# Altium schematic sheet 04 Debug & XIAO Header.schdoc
size 400 x 277 mm; Device: default420x297; Symbol: default420x297; Name: default420x297; Size: "A3"; Id: /; File: 04 Debug & XIAO Header; Sheet: /
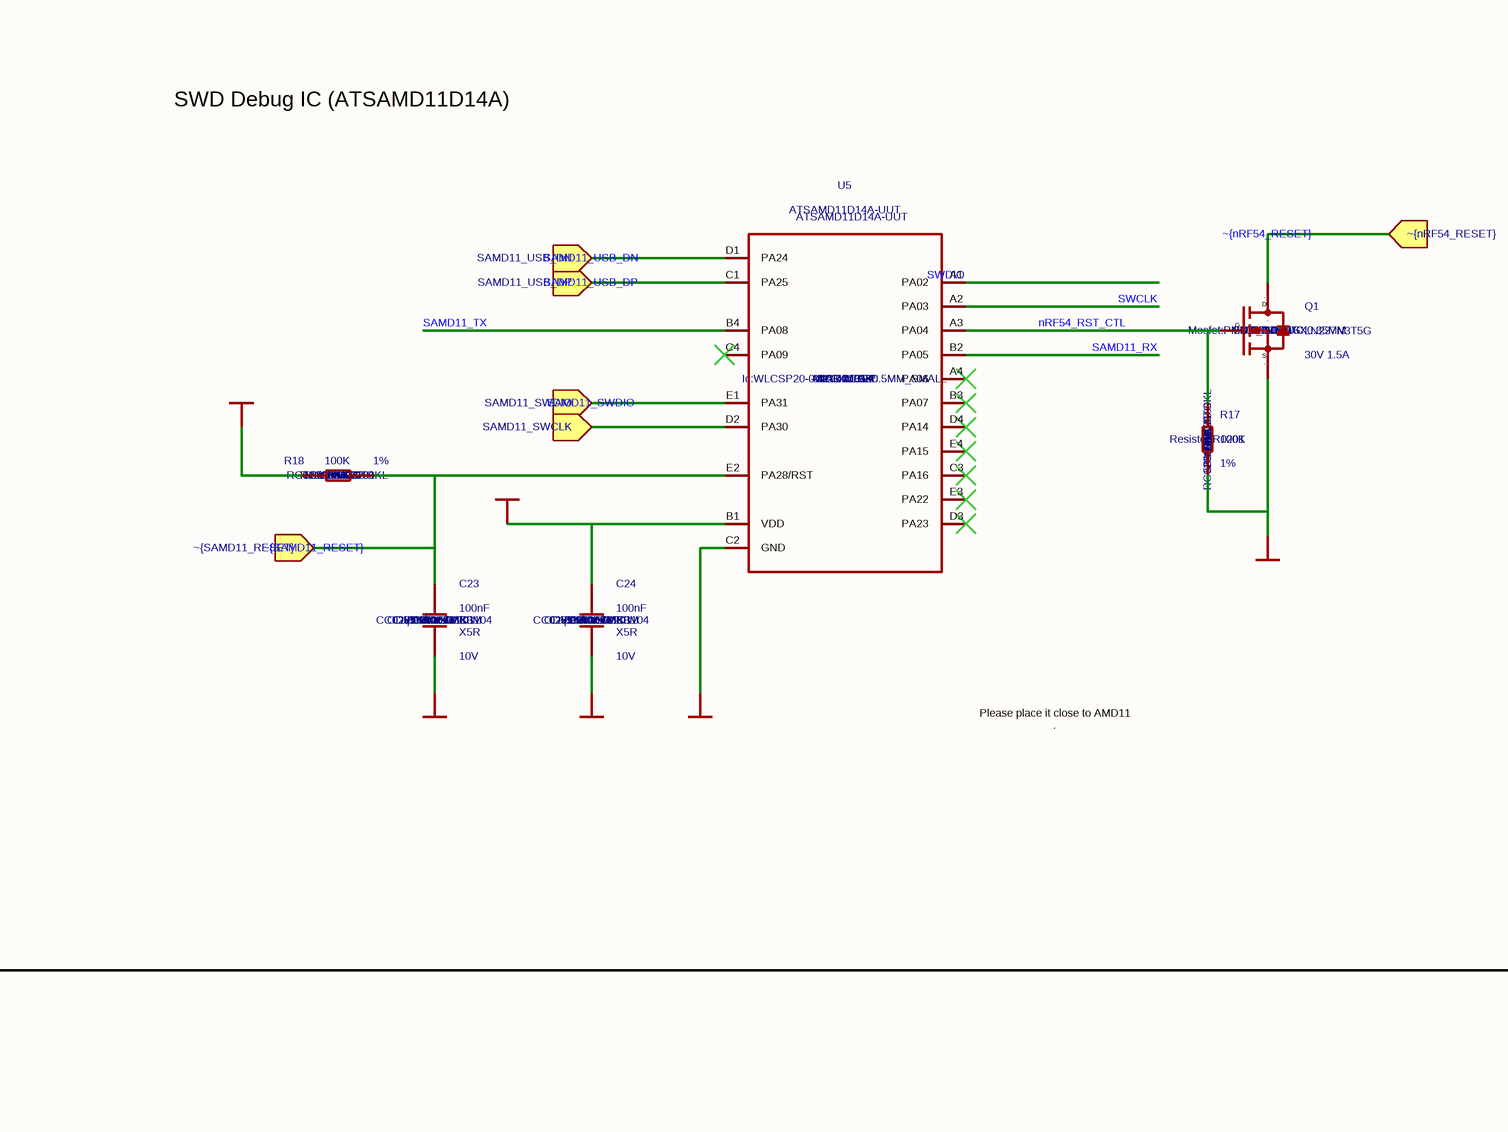
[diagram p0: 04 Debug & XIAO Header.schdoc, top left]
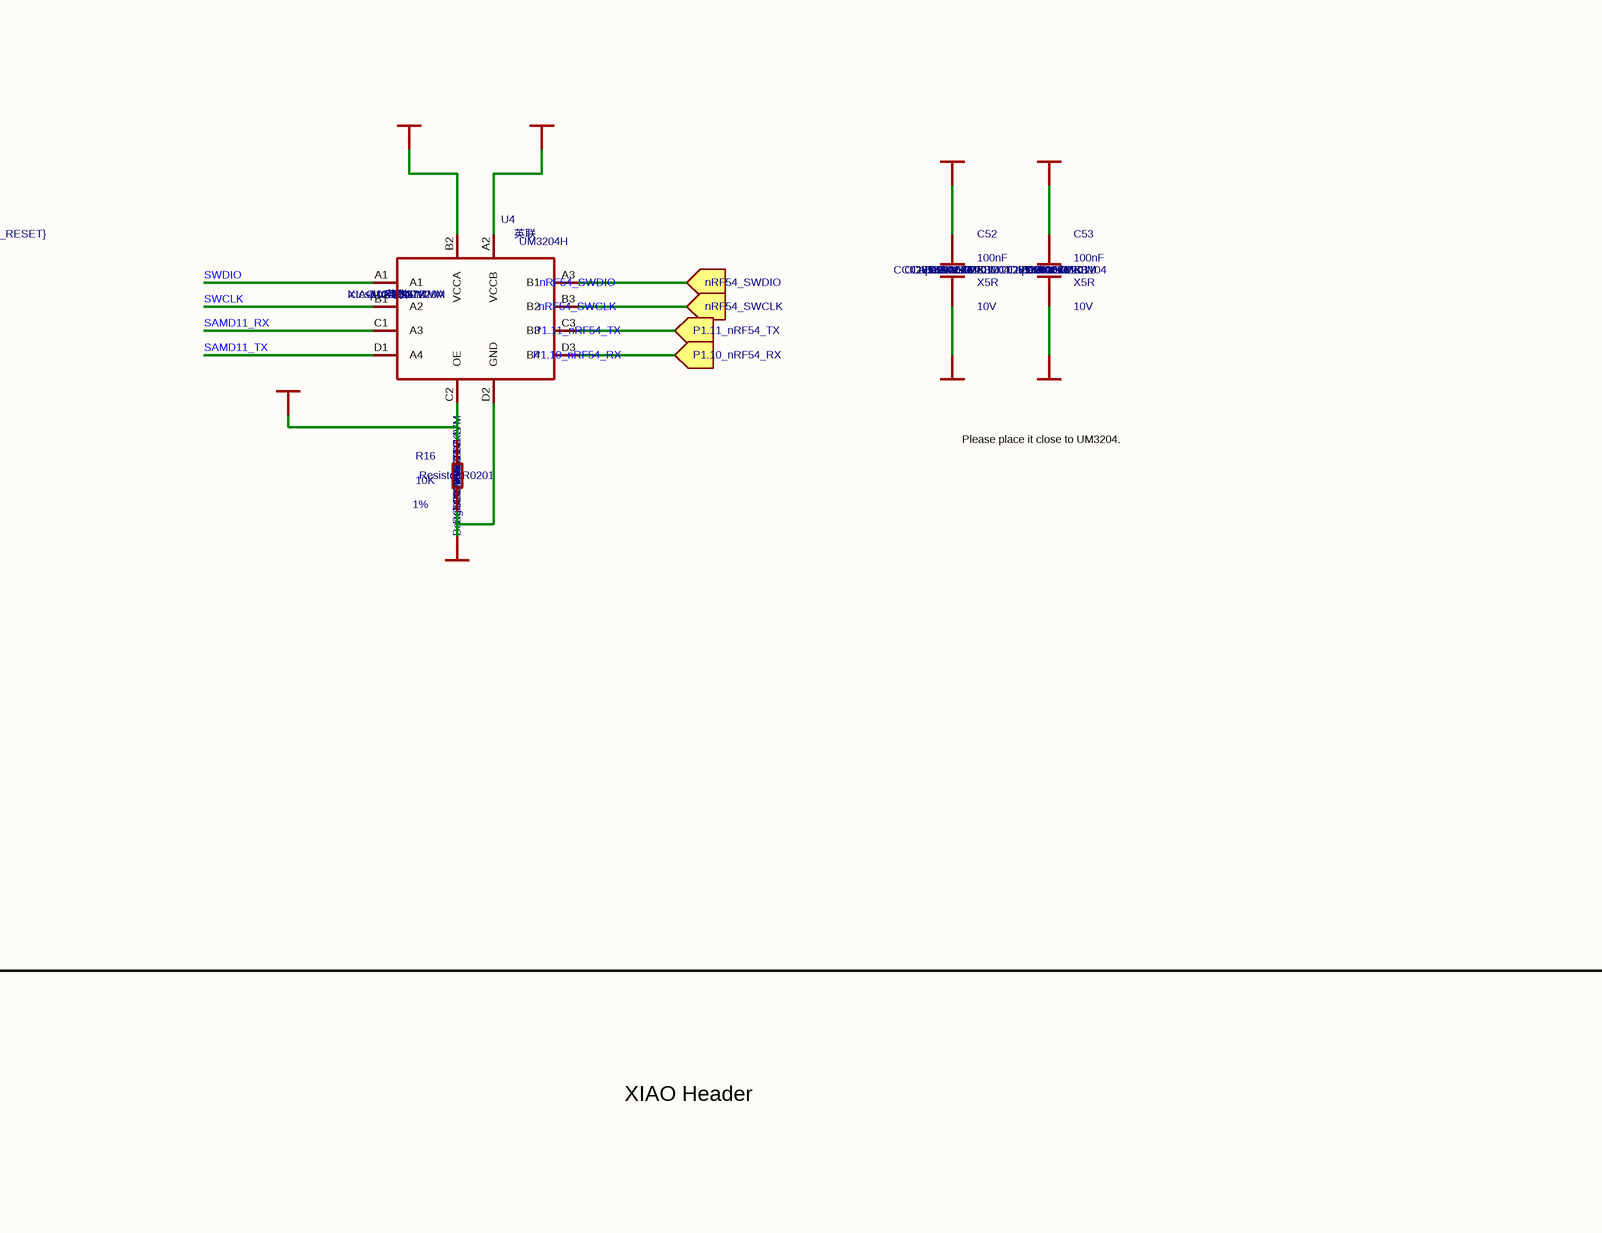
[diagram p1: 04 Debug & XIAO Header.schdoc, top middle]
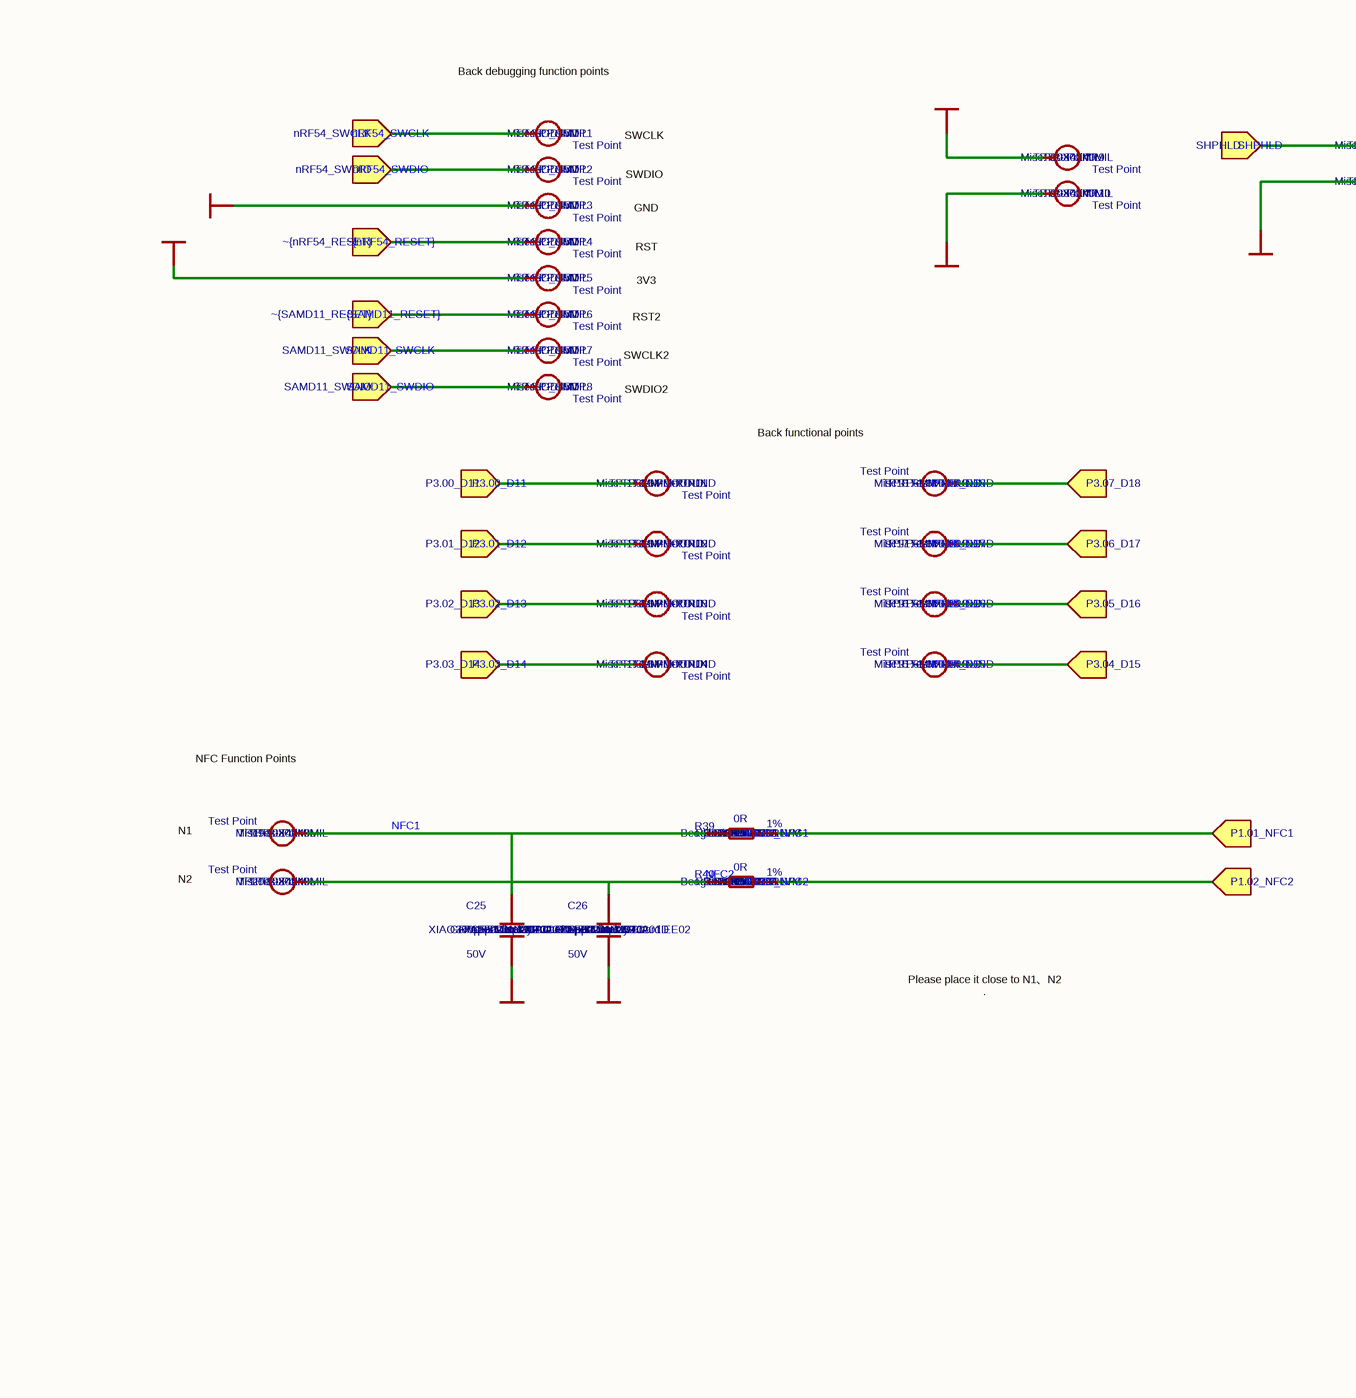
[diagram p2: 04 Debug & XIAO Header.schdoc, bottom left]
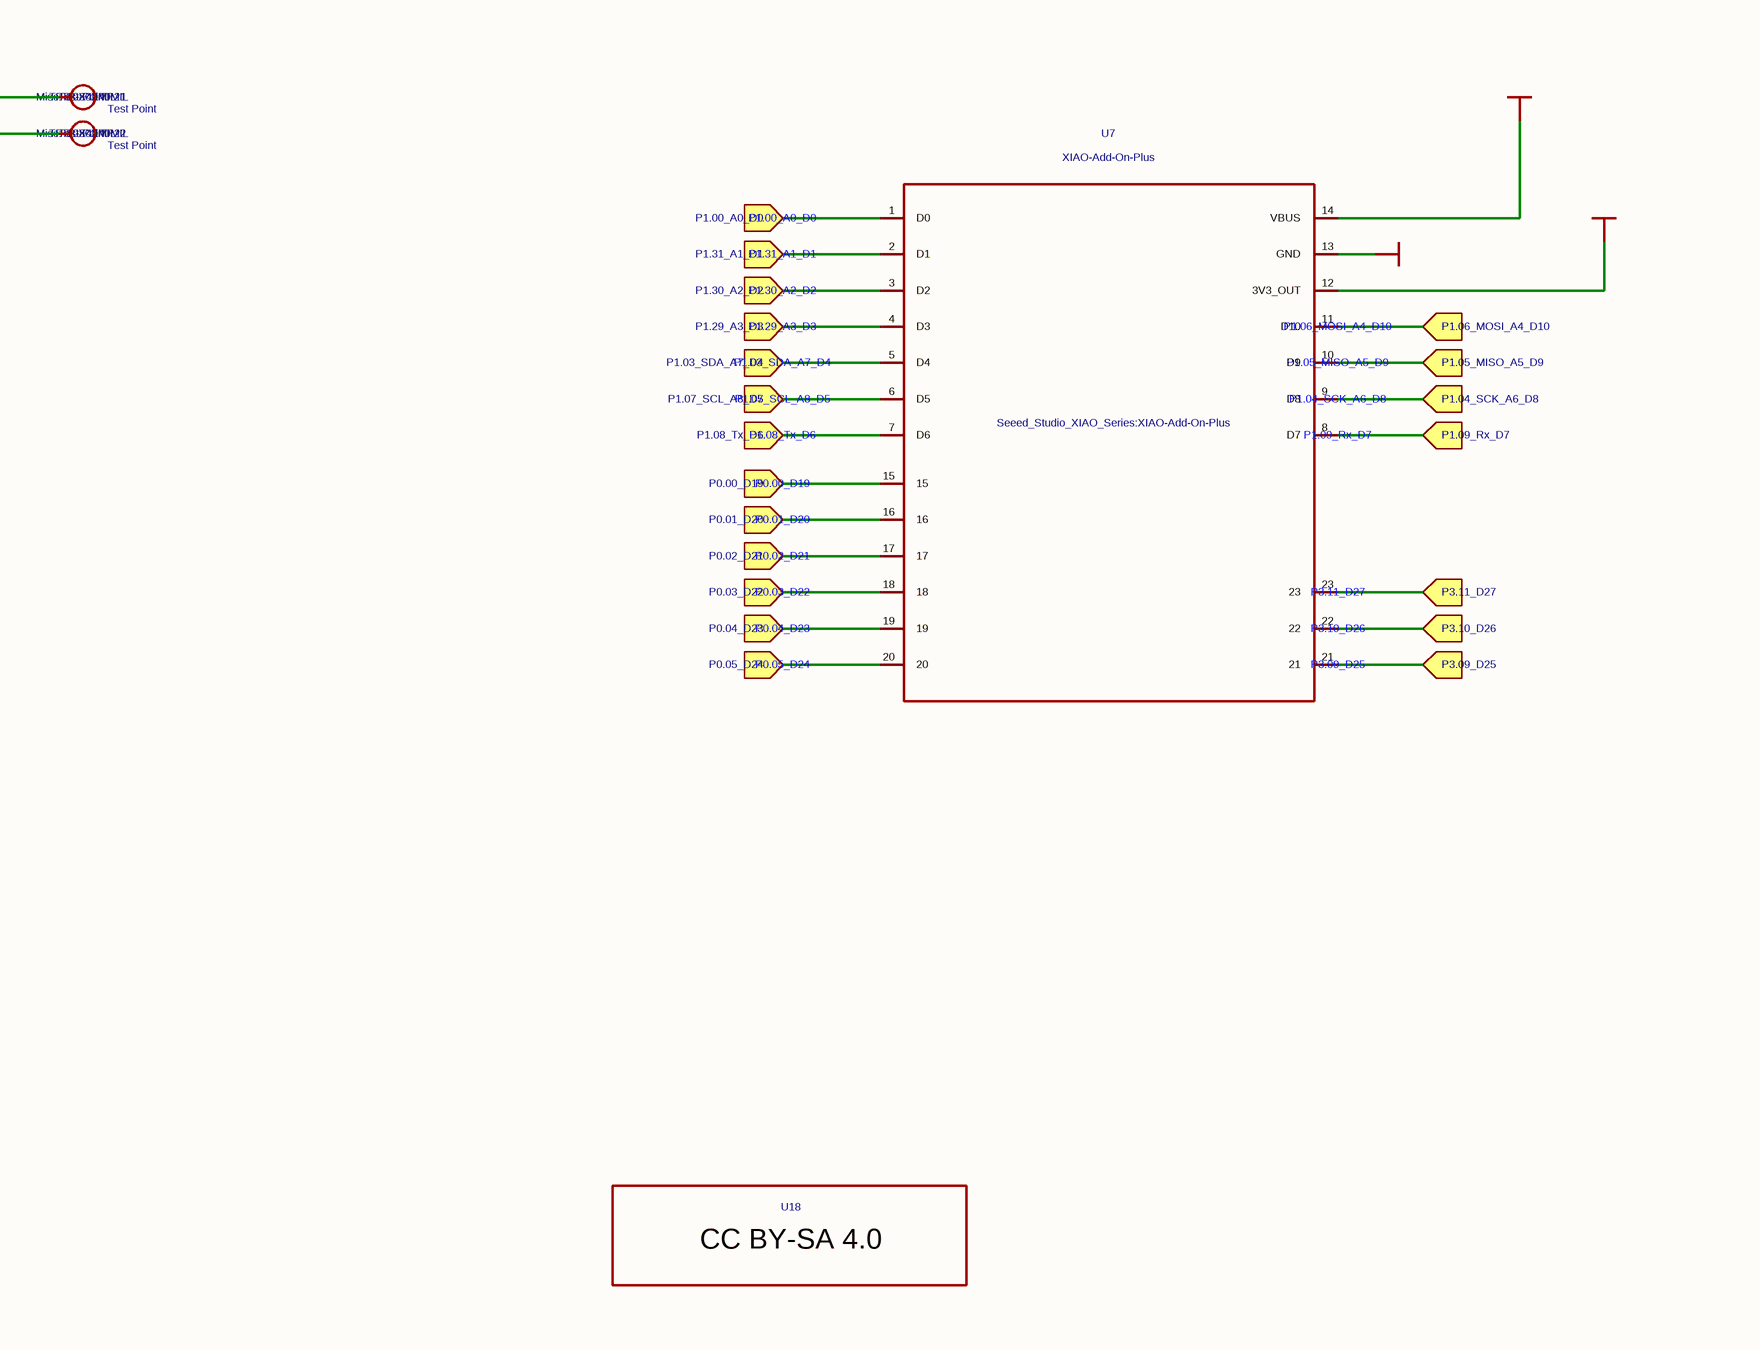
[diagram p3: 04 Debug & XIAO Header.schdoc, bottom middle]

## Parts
C23  value 100nF  Manufacturer: YAGEO  MPN: CC0201KRX5R6BB104  SKU: 302010271  Dielectric: X5R  Part Type: Ceramic  Voltage Rating: 10V  Status: ODYSSEY-i.MX8M  Temperature: -55°C to 85°C  [Capacitor:C0201]  (hidden comment: Seeed_libdb_Capacitors/CA201100NF-SQS4XQ)
C24  value 100nF  Manufacturer: YAGEO  MPN: CC0201KRX5R6BB104  SKU: 302010271  Dielectric: X5R  Part Type: Ceramic  Voltage Rating: 10V  Status: ODYSSEY-i.MX8M  Temperature: -55°C to 85°C  [Capacitor:C0201]  (hidden comment: Seeed_libdb_Capacitors/CA201100NF-SQS4XQ)
C25  value 300pF  Manufacturer: Murata  MPN: GRM1555C1H301JA01D  SKU: 302010759  Voltage Rating: 50V  Status: XIAO ePaper Display Board EE02  Temperature: -55°C to 125°C  [Capacitor:C0402]  (hidden comment: Seeed_libdb_Capacitors/CA402300PF-H353FY)
C26  value 300pF  Manufacturer: Murata  MPN: GRM1555C1H301JA01D  SKU: 302010759  Voltage Rating: 50V  Status: XIAO ePaper Display Board EE02  Temperature: -55°C to 125°C  [Capacitor:C0402]  (hidden comment: Seeed_libdb_Capacitors/CA402300PF-H353FY)
C52  value 100nF  Manufacturer: YAGEO  MPN: CC0201KRX5R6BB104  SKU: 302010271  Dielectric: X5R  Part Type: Ceramic  Voltage Rating: 10V  Status: ODYSSEY-i.MX8M  Temperature: -55°C to 85°C  [Capacitor:C0201]  (hidden comment: Seeed_libdb_Capacitors/CA201100NF-SQS4XQ)
C53  value 100nF  Manufacturer: YAGEO  MPN: CC0201KRX5R6BB104  SKU: 302010271  Dielectric: X5R  Part Type: Ceramic  Voltage Rating: 10V  Status: ODYSSEY-i.MX8M  Temperature: -55°C to 85°C  [Capacitor:C0201]  (hidden comment: Seeed_libdb_Capacitors/CA201100NF-SQS4XQ)
Q1  value LN237N3T5G  Manufacturer: LRC  SKU: 305031600  Part Type: NMOS  Rating: 30V 1.5A  Temperature: -55°C to 150°C  [Mosfet:PMOS_1.0X0.6X0.35MM]  (hidden comment: Seeed_libdb_Mosfet/MO100LN237-JRBPK7)
R16  value 10K  Manufacturer: YAGEO  MPN: RC0201FR-0710KL  SKU: 301010526  Tolerance: 1%  Part Type: RES  Status: BeagleBone AI TDA4VM  Temperature: -55°C to 125°C  [Resistor:R0201]  (hidden comment: Seeed_libdb_Resistors/RE20110K00-N6CP3B)
R17  value 100K  Manufacturer: YAGEO  MPN: RC0201FR-07100KL  SKU: 301010765  Tolerance: 1%  Part Type: RES  Status: XIAO  Temperature: -55°C to 125°C  [Resistor:R0201]  (hidden comment: Seeed_libdb_Resistors/RE201100K0-XFHWYX)
R18  value 100K  Manufacturer: YAGEO  MPN: RC0201FR-07100KL  SKU: 301010765  Tolerance: 1%  Part Type: RES  Status: XIAO  Temperature: -55°C to 125°C  [Resistor:R0201]  (hidden comment: Seeed_libdb_Resistors/RE201100K0-XFHWYX)
R39  value 0R  Manufacturer: YAGEO  MPN: RC0201FR-070RL  SKU: 301010525  Tolerance: 1%  Part Type: RES  Status: BeagleBone AI TDA4VM  Temperature: -55°C to 125°C  [Resistor:R0201]  (hidden comment: Seeed_libdb_Resistors/RE2010R000-2FV3F9)
R40  value 0R  Manufacturer: YAGEO  MPN: RC0201FR-070RL  SKU: 301010525  Tolerance: 1%  Part Type: RES  Status: BeagleBone AI TDA4VM  Temperature: -55°C to 125°C  [Resistor:R0201]  (hidden comment: Seeed_libdb_Resistors/RE2010R000-2FV3F9)
TP1  value Test Point  SKU: TP45C_SMD  [Misc:TP-D45MIL]  (hidden comment: Seeed_libdb_Misc/MI450TESTP-KATXZD)
TP2  value Test Point  SKU: TP45C_SMD  [Misc:TP-D45MIL]  (hidden comment: Seeed_libdb_Misc/MI450TESTP-KATXZD)
TP3  value Test Point  SKU: TP45C_SMD  [Misc:TP-D45MIL]  (hidden comment: Seeed_libdb_Misc/MI450TESTP-KATXZD)
TP4  value Test Point  SKU: TP45C_SMD  [Misc:TP-D45MIL]  (hidden comment: Seeed_libdb_Misc/MI450TESTP-KATXZD)
TP5  value Test Point  SKU: TP45C_SMD  [Misc:TP-D45MIL]  (hidden comment: Seeed_libdb_Misc/MI450TESTP-KATXZD)
TP6  value Test Point  SKU: TP45C_SMD  [Misc:TP-D45MIL]  (hidden comment: Seeed_libdb_Misc/MI450TESTP-KATXZD)
TP7  value Test Point  SKU: TP45C_SMD  [Misc:TP-D45MIL]  (hidden comment: Seeed_libdb_Misc/MI450TESTP-KATXZD)
TP8  value Test Point  SKU: TP45C_SMD  [Misc:TP-D45MIL]  (hidden comment: Seeed_libdb_Misc/MI450TESTP-KATXZD)
TP9  value Test Point  SKU: TP-80X40MIL  [Misc:TP-80X40MIL]  (hidden comment: Seeed_libdb_Misc/MI800TESTP-L5NHTV)
TP10  value Test Point  SKU: TP-80X40MIL  [Misc:TP-80X40MIL]  (hidden comment: Seeed_libdb_Misc/MI800TESTP-L5NHTV)
TP11  value Test Point  SKU: TP-1.6MM-ROUND  [Misc:TP-1.6MM-ROUND]  (hidden comment: Seeed_libdb_Misc/MI100TESTP-YUQ7AE)
TP12  value Test Point  SKU: TP-1.6MM-ROUND  [Misc:TP-1.6MM-ROUND]  (hidden comment: Seeed_libdb_Misc/MI100TESTP-YUQ7AE)
TP13  value Test Point  SKU: TP-1.6MM-ROUND  [Misc:TP-1.6MM-ROUND]  (hidden comment: Seeed_libdb_Misc/MI100TESTP-YUQ7AE)
TP14  value Test Point  SKU: TP-1.6MM-ROUND  [Misc:TP-1.6MM-ROUND]  (hidden comment: Seeed_libdb_Misc/MI100TESTP-YUQ7AE)
TP15  value Test Point  SKU: TP-1.6MM-ROUND  [Misc:TP-1.6MM-ROUND]  (hidden comment: Seeed_libdb_Misc/MI100TESTP-YUQ7AE)
TP16  value Test Point  SKU: TP-1.6MM-ROUND  [Misc:TP-1.6MM-ROUND]  (hidden comment: Seeed_libdb_Misc/MI100TESTP-YUQ7AE)
TP17  value Test Point  SKU: TP-1.6MM-ROUND  [Misc:TP-1.6MM-ROUND]  (hidden comment: Seeed_libdb_Misc/MI100TESTP-YUQ7AE)
TP18  value Test Point  SKU: TP-1.6MM-ROUND  [Misc:TP-1.6MM-ROUND]  (hidden comment: Seeed_libdb_Misc/MI100TESTP-YUQ7AE)
TP19  value Test Point  SKU: TP-80X40MIL  [Misc:TP-80X40MIL]  (hidden comment: Seeed_libdb_Misc/MI800TESTP-L5NHTV)
TP20  value Test Point  SKU: TP-80X40MIL  [Misc:TP-80X40MIL]  (hidden comment: Seeed_libdb_Misc/MI800TESTP-L5NHTV)
TP21  value Test Point  SKU: TP-80X40MIL  [Misc:TP-80X40MIL]  (hidden comment: Seeed_libdb_Misc/MI800TESTP-L5NHTV)
TP22  value Test Point  SKU: TP-80X40MIL  [Misc:TP-80X40MIL]  (hidden comment: Seeed_libdb_Misc/MI800TESTP-L5NHTV)
U4  value 英联  MPN: UM3204H  SKU: 310051371  Part Type: IC  Status: XIAO nRF54LM20A  Temperature: -40°C~85°C  [Ic:csp12-1.9x1.4MM]  (hidden comment: Seeed_libdb_Ic/IC120英联000-CB87J3)
U5  value ATSAMD11D14A-UUT  Manufacturer: MICROCHIP  SKU: 310011816  Status: XIAO MG24  Temperature: -40°C to 85°C  [Ic:WLCSP20-0.4-2.4X1.9X0.5MM_SMALL]  (hidden comment: Seeed_libdb_Ic/IC200ATSAM-XTDBJX)
U7  value XIAO-Add-On-Plus  Origin Footprint: Seeed_Studio_XIAO_Series:XIAO-Add-On-Plus  [Seeed_Studio_XIAO_Series:XIAO-Add-On-PRO]  (hidden comment: Seeed_Studio_XIAO_Series_XIAO-Add-On-Plus)
U18  Misc_LOGO_CC_BY-SA_4.0  [Misc:LOGO_CC_BY-SA_4.0]  (value not drawn)

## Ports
nRF54_SWCLK (in), nRF54_SWDIO (in), P0.00_D19 (in), P0.01_D20 (in), P0.02_D21 (in), P0.03_D22 (in), P0.04_D23 (in), P0.05_D24 (in), P1.00_A0_D0 (in), P1.01_NFC1 (in), P1.02_NFC2 (in), P1.03_SDA_A7_D4 (in), P1.04_SCK_A6_D8 (in), P1.05_MISO_A5_D9 (in), P1.06_MOSI_A4_D10 (in), P1.07_SCL_A8_D5 (in), P1.08_Tx_D6 (in), P1.09_Rx_D7 (in), P1.10_nRF54_RX (in), P1.11_nRF54_TX (in), P1.29_A3_D3 (in), P1.30_A2_D2 (in), P1.31_A1_D1 (in), P3.00_D11 (in), P3.01_D12 (in), P3.02_D13 (in), P3.03_D14 (in), P3.04_D15 (in), P3.05_D16 (in), P3.06_D17 (in), P3.07_D18 (in), P3.09_D25 (in), P3.10_D26 (in), P3.11_D27 (in), SAMD11_SWCLK (in), SAMD11_SWDIO (in), SAMD11_USB_DN (in), SAMD11_USB_DP (in), SHPHLD (in), ~{nRF54_RESET} (in), ~{SAMD11_RESET} (in)

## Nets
power_+5V: C24.1 C52.1 C53.1 R16.1 R18.2 TP5.1(T) TP9.1(T) U4.A2(VCCB) U4.B2(VCCA) U4.C2(OE) U5.B1(VDD) U7.12(3V3_OUT) U7.14(VBUS)
Power_Gnd_GNDREF: C23.2 C24.2 C25.2 C26.2 C52.2 C53.2 Q1.2(S) R16.2 R17.1 TP3.1(T) TP10.1(T) TP22.1(T) U4.D2(GND) U5.C2(GND) U7.13(GND)
NFC1: C25.1 R39.2 TP19.1(T)
NFC2: C26.1 R40.2 TP20.1(T)
nRF54_RST_CTL: Q1.1(G) R17.2 U5.A3(PA04)
nRF54_SWCLK: TP1.1(T) U4.B3(B2) ; port nRF54_SWCLK
nRF54_SWDIO: TP2.1(T) U4.A3(B1) ; port nRF54_SWDIO
P0.00_D19: U7.15 ; port P0.00_D19
P0.01_D20: U7.16 ; port P0.01_D20
P0.02_D21: U7.17 ; port P0.02_D21
P0.03_D22: U7.18 ; port P0.03_D22
P0.04_D23: U7.19 ; port P0.04_D23
P0.05_D24: U7.20 ; port P0.05_D24
P1.00_A0_D0: U7.1(D0) ; port P1.00_A0_D0
P1.01_NFC1: R39.1 ; port P1.01_NFC1
P1.02_NFC2: R40.1 ; port P1.02_NFC2
P1.03_SDA_A7_D4: U7.5(D4) ; port P1.03_SDA_A7_D4
P1.04_SCK_A6_D8: U7.9(D8) ; port P1.04_SCK_A6_D8
P1.05_MISO_A5_D9: U7.10(D9) ; port P1.05_MISO_A5_D9
P1.06_MOSI_A4_D10: U7.11(D10) ; port P1.06_MOSI_A4_D10
P1.07_SCL_A8_D5: U7.6(D5) ; port P1.07_SCL_A8_D5
P1.08_Tx_D6: U7.7(D6) ; port P1.08_Tx_D6
P1.09_Rx_D7: U7.8(D7) ; port P1.09_Rx_D7
P1.10_nRF54_RX: U4.D3(B4) ; port P1.10_nRF54_RX
P1.11_nRF54_TX: U4.C3(B3) ; port P1.11_nRF54_TX
P1.29_A3_D3: U7.4(D3) ; port P1.29_A3_D3
P1.30_A2_D2: U7.3(D2) ; port P1.30_A2_D2
P1.31_A1_D1: U7.2(D1) ; port P1.31_A1_D1
P3.00_D11: TP11.1(T) ; port P3.00_D11
P3.01_D12: TP12.1(T) ; port P3.01_D12
P3.02_D13: TP13.1(T) ; port P3.02_D13
P3.03_D14: TP14.1(T) ; port P3.03_D14
P3.04_D15: TP15.1(T) ; port P3.04_D15
P3.05_D16: TP16.1(T) ; port P3.05_D16
P3.06_D17: TP17.1(T) ; port P3.06_D17
P3.07_D18: TP18.1(T) ; port P3.07_D18
P3.09_D25: U7.21 ; port P3.09_D25
P3.10_D26: U7.22 ; port P3.10_D26
P3.11_D27: U7.23 ; port P3.11_D27
SAMD11_RX: U4.C1(A3) U5.B2(PA05)
SAMD11_SWCLK: TP7.1(T) U5.D2(PA30) ; port SAMD11_SWCLK
SAMD11_SWDIO: TP8.1(T) U5.E1(PA31) ; port SAMD11_SWDIO
SAMD11_TX: U4.D1(A4) U5.B4(PA08)
SAMD11_USB_DN: U5.D1(PA24) ; port SAMD11_USB_DN
SAMD11_USB_DP: U5.C1(PA25) ; port SAMD11_USB_DP
SHPHLD: TP21.1(T) ; port SHPHLD
SWCLK: U4.B1(A2) U5.A2(PA03)
SWDIO: U4.A1 U5.A1(PA02)
~{nRF54_RESET}: Q1.3(D) TP4.1(T) ; port ~{nRF54_RESET}
~{SAMD11_RESET}: C23.1 R18.1 TP6.1(T) U5.E2(PA28/RST) ; port ~{SAMD11_RESET}

Not connected (* = marked no-connect by the designer): U5 A4(PA06)* B3(PA07)* C3(PA16)* C4(PA09)* D3(PA23)* D4(PA14)* E3(PA22)* E4(PA15)*

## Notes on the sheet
- SWD Debug IC (ATSAMD11D14A)
- Please place it close to UM3204.
- Please place it close to AMD11
  .
- (near TP1) Back debugging function points
- XIAO Header
- SWDIO
- SWCLK
- 3V3
- RST
- RST2
- GND
- SWCLK2
- SWDIO2
- Back functional points
- (near TP19) NFC Function Points
- N1
- N2
- Please place it close to N1、N2
  .

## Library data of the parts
C23 = Seeed_libdb_Capacitors/CA201100NF-SQS4XQ: SMD CAP Ceramic 100nF-10V-10%-X5R;0201; UniqueId: 8bc5c1e1749a19fa; AddInBom: yes
C24 = Seeed_libdb_Capacitors/CA201100NF-SQS4XQ: SMD CAP Ceramic 100nF-10V-10%-X5R;0201; UniqueId: 7c674fedd66d7165; AddInBom: yes
C25 = Seeed_libdb_Capacitors/CA402300PF-H353FY: SMD CAP Ceramic 300pF-50V-5%-NPO;0402; UniqueId: d99985aa138ce050; AddInBom: yes
C26 = Seeed_libdb_Capacitors/CA402300PF-H353FY: SMD CAP Ceramic 300pF-50V-5%-NPO;0402; UniqueId: 5bc8fc857418e778; AddInBom: yes
C52 = Seeed_libdb_Capacitors/CA201100NF-SQS4XQ: SMD CAP Ceramic 100nF-10V-10%-X5R;0201; UniqueId: 35d858017be1d91e; AddInBom: yes
C53 = Seeed_libdb_Capacitors/CA201100NF-SQS4XQ: SMD CAP Ceramic 100nF-10V-10%-X5R;0201; UniqueId: af7046427a4bfdfb; AddInBom: yes
Q1 = Seeed_libdb_Mosfet/MO100LN237-JRBPK7: SMD MOSFET N-CH 30V-1.5A;SOT-883; UniqueId: f76c01de5337d462; AddInBom: yes
R16 = Seeed_libdb_Resistors/RE20110K00-N6CP3B: SMD RES 10K-±1%-1/20W;0201; UniqueId: 3c543c7c58e1cc80; AddInBom: yes
R17 = Seeed_libdb_Resistors/RE201100K0-XFHWYX: SMD RES 100K-±1%-1/20W;0201; UniqueId: 6346d187b4e0bc9c; AddInBom: yes
R18 = Seeed_libdb_Resistors/RE201100K0-XFHWYX: SMD RES 100K-±1%-1/20W;0201; UniqueId: 5f673669f0d56d8f; AddInBom: yes
R39 = Seeed_libdb_Resistors/RE2010R000-2FV3F9: SMD RES 0R-±1%-1/20W;0201; UniqueId: 61aee2c7162d13e5; AddInBom: yes
R40 = Seeed_libdb_Resistors/RE2010R000-2FV3F9: SMD RES 0R-±1%-1/20W;0201; UniqueId: 5d7d37af6db8001c; AddInBom: yes
TP1 = Seeed_libdb_Misc/MI450TESTP-KATXZD: Test Point;TP45C_SMD; UniqueId: 4726d92b84fba278; AddInBom: yes
TP2 = Seeed_libdb_Misc/MI450TESTP-KATXZD: Test Point;TP45C_SMD; UniqueId: 21ffbae72f4f4154; AddInBom: yes
TP3 = Seeed_libdb_Misc/MI450TESTP-KATXZD: Test Point;TP45C_SMD; UniqueId: 8df4c48c9acaaf69; AddInBom: yes
TP4 = Seeed_libdb_Misc/MI450TESTP-KATXZD: Test Point;TP45C_SMD; UniqueId: 6410be24ff53b3b6; AddInBom: yes
TP5 = Seeed_libdb_Misc/MI450TESTP-KATXZD: Test Point;TP45C_SMD; UniqueId: f7ec211fb22f3ea3; AddInBom: yes
TP6 = Seeed_libdb_Misc/MI450TESTP-KATXZD: Test Point;TP45C_SMD; UniqueId: 84aa4de12bc2747c; AddInBom: yes
TP7 = Seeed_libdb_Misc/MI450TESTP-KATXZD: Test Point;TP45C_SMD; UniqueId: 7a581efd1dfccb02; AddInBom: yes
TP8 = Seeed_libdb_Misc/MI450TESTP-KATXZD: Test Point;TP45C_SMD; UniqueId: 375a2f0a72128209; AddInBom: yes
TP9 = Seeed_libdb_Misc/MI800TESTP-L5NHTV: Test Point;TP80X40_SMD; UniqueId: b8330ba4c2366313; AddInBom: yes
TP10 = Seeed_libdb_Misc/MI800TESTP-L5NHTV: Test Point;TP80X40_SMD; UniqueId: 2ec9ca781fac6d98; AddInBom: yes
TP11 = Seeed_libdb_Misc/MI100TESTP-YUQ7AE: Test Point;TP-1.6MM-ROUND; UniqueId: 5c017d4c6155c13a; AddInBom: yes
TP12 = Seeed_libdb_Misc/MI100TESTP-YUQ7AE: Test Point;TP-1.6MM-ROUND; UniqueId: 8c1c3e1ea446fec8; AddInBom: yes
TP13 = Seeed_libdb_Misc/MI100TESTP-YUQ7AE: Test Point;TP-1.6MM-ROUND; UniqueId: 8795cd014da59b31; AddInBom: yes
TP14 = Seeed_libdb_Misc/MI100TESTP-YUQ7AE: Test Point;TP-1.6MM-ROUND; UniqueId: 58e6419f7fdb801e; AddInBom: yes
TP15 = Seeed_libdb_Misc/MI100TESTP-YUQ7AE: Test Point;TP-1.6MM-ROUND; UniqueId: ff17f23543f2d05d; AddInBom: yes
TP16 = Seeed_libdb_Misc/MI100TESTP-YUQ7AE: Test Point;TP-1.6MM-ROUND; UniqueId: 77b4ec4692ae36ae; AddInBom: yes
TP17 = Seeed_libdb_Misc/MI100TESTP-YUQ7AE: Test Point;TP-1.6MM-ROUND; UniqueId: e2e02d30e62e07ab; AddInBom: yes
TP18 = Seeed_libdb_Misc/MI100TESTP-YUQ7AE: Test Point;TP-1.6MM-ROUND; UniqueId: fdb2fd124e3ba50f; AddInBom: yes
TP19 = Seeed_libdb_Misc/MI800TESTP-L5NHTV: Test Point;TP80X40_SMD; UniqueId: f21d787f64890846; AddInBom: yes
TP20 = Seeed_libdb_Misc/MI800TESTP-L5NHTV: Test Point;TP80X40_SMD; UniqueId: 921d800968e9e831; AddInBom: yes
TP21 = Seeed_libdb_Misc/MI800TESTP-L5NHTV: Test Point;TP80X40_SMD; UniqueId: f8e4b79be9cbe423; AddInBom: yes
TP22 = Seeed_libdb_Misc/MI800TESTP-L5NHTV: Test Point;TP80X40_SMD; UniqueId: 638914a9004373a8; AddInBom: yes
U4 = Seeed_libdb_Ic/IC120英联000-CB87J3: SMD IC Level translator;Bidirectional-4-CH;CSP-12; UniqueId: bac468049775df37; AddInBom: yes
U5 = Seeed_libdb_Ic/IC200ATSAM-XTDBJX: SMD IC MCU;ARM Cortex-MO+32-bit-48 MHz-16KB Flash;WLCSP-20; UniqueId: adf583383e4d69d4; AddInBom: yes
U7 = Seeed_Studio_XIAO_Series_XIAO-Add-On-Plus: UniqueId: 4ec783ed4741de1f; AddInBom: yes
U18 = Misc_LOGO_CC_BY-SA_4.0: UniqueId: 3b01714176430545; AddInBom: yes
